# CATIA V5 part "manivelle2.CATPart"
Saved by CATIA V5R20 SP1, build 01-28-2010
Part number: manivelle2
Bounding box of the stored display mesh (mm): x -10 to 20, y 33.412 to 75.405, z 17.847 to 105.852
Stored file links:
  E:\EDELI\gcausse\Edeli_2012_613_gcausse\manivelle2.CATPart
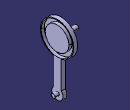
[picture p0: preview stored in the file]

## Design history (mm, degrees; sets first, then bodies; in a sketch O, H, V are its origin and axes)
Body1 (main body)
  DatumSurface1
  Sketch1 on face of DatumSurface1, origin (10, 0, 0), H (0, 1, 0), V (0, 0, 1)
    line L1 (49.7014, 64.3878) -> (49.7014, 30)
    line L2 (59.7014, 64.5333) -> (59.7014, 30)
    arc A1 centre (54.7014, 24.855) radius 7.1743 from (59.7014, 30) to (49.7014, 30) cw
    point P5 (54.7014, 24.855)
    arc A2 centre (54.4047, 84.8543) radius 21 from (59.7014, 64.5333) to (49.7014, 64.3878) ccw
    point P6 (54.4047, 84.8543)
    circle A3 centre (54.4047, 84.8543) radius 14
    radius A3 = 14
    radius A2 = 21
    distance P5 L2 = 5
    distance L1 L2 = 10
    distance P5 P6 = 60
    vertical: L1 V, L2 V
  Pad1: profile Sketch1, direction (1, 0, 0), length 5
  Sketch2 on end face of Pad1, origin (15, 0, 0), H (0, 1, 0), V (0, 0, 1)
    circle A1 centre (54.4047, 84.8543) radius 15
    circle A2 centre (54.4047, 84.8543) radius 20
    reference projected arc E1 centre (54.4047, 84.8543) radius 21 from (59.7291, 64.5405) to (49.7291, 64.3814) ccw from edge [face of Pad1 from Sketch1.A2 | end face of Pad1]
    radius A1 = 15
    radius A2 = 20
    concentricity: A2 E1
  Pocket1: profile Sketch2, direction (-1, 0, 0), length 4
  Sketch3 on end face of Pad1, origin (15, 0, 0), H (0, 1, 0), V (0, 0, 1)
    circle A1 centre (54.4047, 84.8543) radius 14
    reference projected circle E1 centre (54.4047, 84.8543) radius 14 from edge [end face of Pad1 | face of Pad1 from Sketch1.A3]
    reference projected circle E2 centre (54.4047, 84.8543) radius 14 from edge [end face of Pad1 | face of Pad1 from Sketch1.A3]
    radius A1 = 14
    radius E2 = 14 (reference)
    concentricity: A1 E1
  Pad2: profile Sketch3, direction (-1, 0, 0), length 5
  Sketch4 on face of Pad2, origin (10, 0, 0), H (0, -1, 0), V (0, 0, 1)
    circle A1 centre (-54.4047, 84.8543) radius 2.5
    reference projected arc E1 centre (-54.4047, 84.8543) radius 21 from (-49.7291, 64.3814) to (-59.7291, 64.5405) ccw from edge [start face of Pad1 | face of Pad1 from Sketch1.A2]
    radius A1 = 2.5
    concentricity: A1 E1
  Pad3: profile Sketch4, direction (-1, 0, 0), length 20
  Sketch5 on end face of Pad1, origin (15, 0, 0), H (0, 1, 0), V (0, 0, 1)
    circle A1 centre (54.7014, 24.855) radius 2.5
    reference projected arc E1 centre (54.7014, 24.855) radius 7.1743 from (49.7014, 30) to (59.7014, 30) ccw from edge [face of Pad1 from Sketch1.A1 | end face of Pad1]
    radius A1 = 2.5
    concentricity: A1 E1
  Pad4: profile Sketch5, direction (1, 0, 0), length 5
